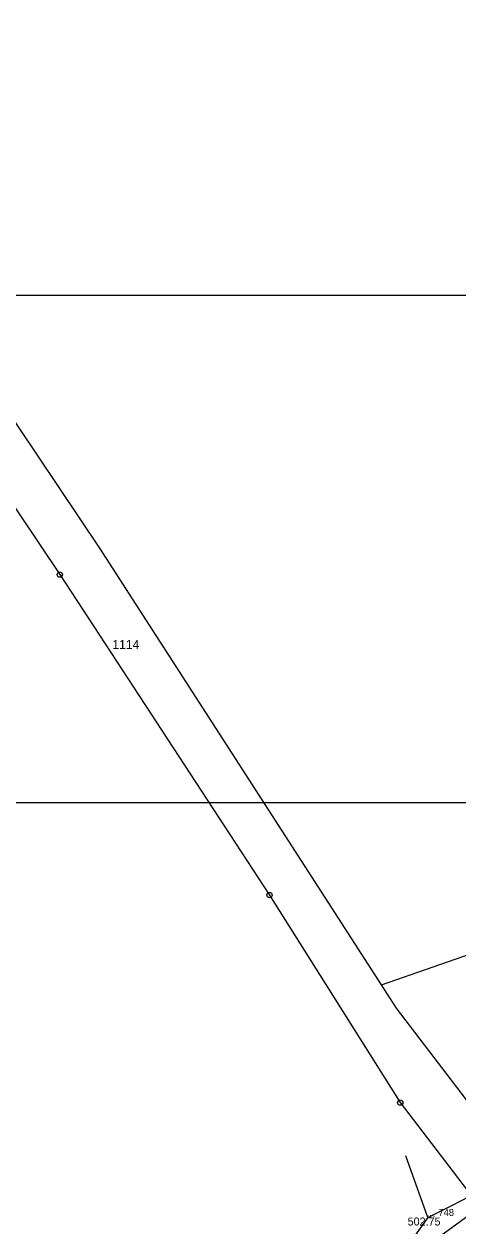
# Model space of a CAD drawing. Extents: x -604848 to -603227, y -1111879 to -1109838.
# Drawn here: x -604015.2 to -603934, y -1110757.2 to -1110531.9 of the extents above; entities that cross this region are included whole.
import ezdxf

# ---------------------------------------------------------------- set-up
doc = ezdxf.new("R2010")
doc.units = 0
for name, color, linetype in [('1', 7, 'Continuous'), ('10', 7, 'Continuous'), ('14', 7, 'Continuous'), ('18', 7, 'Continuous'), ('19', 7, 'Continuous'), ('20', 7, 'Continuous'), ('28', 7, 'Continuous'), ('Default', 7, 'Continuous')]:
    doc.layers.add(name, color=color, linetype=linetype)

# ---------------------------------------------------------------- blocks, each defined once
blk = doc.blocks.new('Z105')
at = {"layer": '28'}
for radius in [0.5, 0.01]:
    blk.add_circle((0, 0), radius, dxfattribs=at)
blk = doc.blocks.new('POINT_DISPLAY')
at = {"layer": 'Default'}
blk.add_line((0, 0), (0, 0), dxfattribs=at)

msp = doc.modelspace()

# ---------------------------------------------------------------- linework, layer by layer
at = {"layer": '1'}
for p, q in [((-604001.03, -1110630.12), (-604033.85, -1110581.25)), ((-604040.18, -1110587.97), (-604008.53, -1110635.09)), ((-603948.31, -1110711.99), (-604001.03, -1110630.12)), ((-604008.53, -1110635.09), (-603969.27, -1110695.15)), ((-603948.31, -1110711.99), (-603821.12, -1110667.42)), ((-603969.27, -1110695.15), (-603944.79, -1110734.04)), ((-603945.51, -1110716.34), (-603948.31, -1110711.99)), ((-603926.93, -1110740.69), (-603945.51, -1110716.34)), ((-603944.79, -1110734.04), (-603929.83, -1110753.64)), ((-603929.83, -1110753.64), (-604011.5, -1110813.05))]:
    msp.add_line(p, q, dxfattribs=at)
for points in [[(-603752.05, -1110677.81), (-603752.05, -1109837.81), (-604346.05, -1109837.81), (-604346.05, -1110677.81), (-603752.05, -1110677.81)], [(-603781.41, -1111422.77), (-603781.41, -1110582.77), (-604375.41, -1110582.77), (-604375.41, -1111422.77), (-603781.41, -1111422.77)]]:
    msp.add_lwpolyline(points, dxfattribs=at)
at = {"layer": '10'}
for q in [(-603943.74, -1110744.01), (-603917.59, -1110744.4), (-603947.26, -1110766.17)]:
    msp.add_line((-603939.62, -1110755.58), q, dxfattribs=at)

# ---------------------------------------------------------------- block references
at = {"layer": '18'}
msp.add_blockref('POINT_DISPLAY', (-603939.62, -1110755.58), dxfattribs=at)
at = {"layer": '28'}
for p in [(-604008.53, -1110635.09), (-603969.27, -1110695.15), (-603944.79, -1110734.04)]:
    msp.add_blockref('Z105', p, dxfattribs=at)

# ---------------------------------------------------------------- texts
at = {"layer": '14'}
msp.add_text('1114', height=1.7, dxfattribs=at).set_placement((-603998.7, -1110649.05))
at = {"layer": '18'}
msp.add_text('LES', height=0.5, dxfattribs=at).set_placement((-603939.62, -1110755.58))
at = {"layer": '19'}
msp.add_text('748', height=1.3, dxfattribs=at).set_placement((-603937.62, -1110755.28))
at = {"layer": '20'}
msp.add_text('502.75 ', height=1.5, dxfattribs=at).set_placement((-603943.39, -1110757.08))

doc.saveas('drawing.dxf')
